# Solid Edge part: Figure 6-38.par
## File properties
Author: CADCIM
Template: Normal.par
Last saved by: CADCIM
Revision: 6
Application: Solid Edge
Accuracy: 0.99
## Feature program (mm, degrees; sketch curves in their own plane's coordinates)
sketch for "unnamed Protrusion 1" plane through (0, 0, 0) normal (0, -1, 0) x-axis (1, 0, 0)
  line (-50, 0) -> (50, 0)
  line (50, 0) -> (45, 10)
  line (45, 10) -> (-45, 10)
  line (-45, 10) -> (-50, 0)
extrude "unnamed Protrusion 1" add finite 120 symmetric
sketch for "unnamed Cutout 1" plane through (0, 0, 10) normal (0, 0, 1) x-axis (0, 1, 0)
  line (-45, -25) -> (-30, -25)
  arc centre (-30, -30) radius 5 from (-30, -25) to (-30, -35) cw
  line (-45, -35) -> (-30, -35)
  arc centre (-45, -30) radius 5 from (-45, -35) to (-45, -25) cw
extrude "unnamed Cutout 1" cut through along -normal
pattern "unnamed Pattern 1" of "unnamed Cutout 1"
extrude "unnamed Cutout 2" cut through
extrude "unnamed Cutout 3" cut through
extrude "unnamed Cutout 4" cut through
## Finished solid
Body 1: solid body, 22 faces, 60 edges, 40 vertices.
  Faces by surface: plane 14, cylinder 8
  Edges by curve: line 44, circle 16
Bounding box of the edges (mm): 100.000 x 120.000 x 10.000, from (-50, -60, 0) to (50, 60, 10).
Cylindrical faces by radius (mm): R5 x8
Planar faces by outward normal: +x 4, +y 1, +z 1, -x 4, -y 1, -z 1, oblique 2
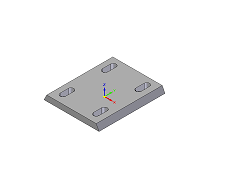
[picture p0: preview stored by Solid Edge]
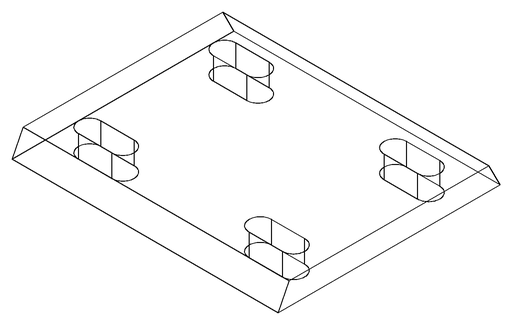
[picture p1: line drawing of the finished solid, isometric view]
